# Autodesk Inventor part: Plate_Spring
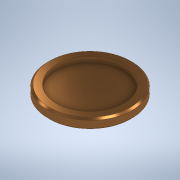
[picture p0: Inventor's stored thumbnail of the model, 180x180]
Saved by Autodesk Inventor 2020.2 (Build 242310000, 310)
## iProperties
Created: 2020-01
Part Number: Plate_Spring
Material: Steel, Carbon
Document SubType Name: Modeling
Designer: thira
Density: 7.85 g/cm^3
Appearance: Semi-Polished
Author: thira
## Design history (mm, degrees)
sketch "Sketch1"
  geometry: C1 r 100 at (0, 0); C2 r 125 at (0, 0); 1 further point
  constraints: 2 centre point, 2 coincident
  dimensions: "d0" = 200 diameter of C1; "d1" = 250 diameter of C2
extrude "Extrusion1" new body sketch "Sketch1" distance "d2" = 30; taper "d3" = 0 deg
extrude "Extrusion2" cut sketch "Sketch1" distance "d4" = 15; taper "d5" = 0 deg
chamfer "Chamfer1" distance "d6" = 5; stored, may be unused: second distance "d7" = 2, angle "d8" = 45 deg
chamfer "Chamfer2" distance "d9" = 5; stored, may be unused: second distance "d10" = 2, angle "d11" = 45 deg
body "Solid1"
